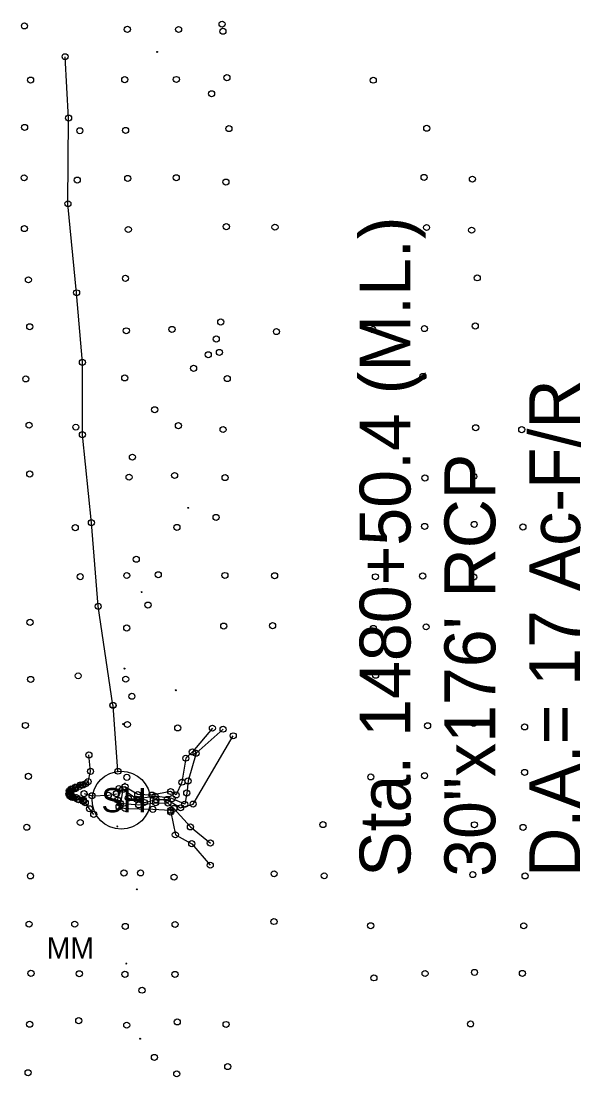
# Model space of a CAD drawing. Extents: x 20503438 to 20508873, y 7964251 to 7984667.
# Drawn here: x 20505530.1 to 20505714.9, y 7980570.4 to 7980918.8 of the extents above; entities that cross this region are included whole.
import ezdxf

# ---------------------------------------------------------------- set-up
doc = ezdxf.new("R2010")
doc.units = 0
for name, color, linetype in [('SurBreakLine', 7, 'Continuous'), ('SurConcreteSlab', 7, 'Continuous'), ('SurControl', 7, 'Continuous'), ('SurDrainageArrowDown', 7, 'Continuous'), ('SurDrainageArrowUp', 7, 'Continuous'), ('SurNaturalCells', 7, 'Continuous'), ('SurPointsNonDTM', 7, 'Continuous'), ('SurRoadPoints', 7, 'Continuous'), ('SurSurveyPoints', 7, 'Continuous'), ('SurTopOfWater', 7, 'Continuous'), ('SurTxtDrainage', 7, 'Continuous')]:
    doc.layers.add(name, color=color, linetype=linetype)

msp = doc.modelspace()

# ---------------------------------------------------------------- linework, layer by layer
at = {"layer": 'SurBreakLine'}
for points in [[(20505593.25, 7980685.48), (20505586.62, 7980677.63), (20505584.46, 7980675.57), (20505583.18, 7980667.65), (20505581.29, 7980663.44), (20505579.46, 7980664.57), (20505573.29, 7980663.41), (20505568.59, 7980663.55), (20505564.39, 7980666.13), (20505562.35, 7980665.55), (20505561.96, 7980661.76), (20505562.45, 7980659.56), (20505564.42, 7980658.97), (20505573.58, 7980658.7), (20505579.42, 7980658.39), (20505579.48, 7980657.79), (20505581.01, 7980650.28), (20505586.41, 7980647.36), (20505592.52, 7980640.26)], [(20505596.76, 7980685.14), (20505587.84, 7980677.2), (20505585.2, 7980668.06), (20505584.76, 7980664.08), (20505584.12, 7980660.36), (20505579.9, 7980662.22), (20505574.32, 7980663.04), (20505568.35, 7980662.01), (20505563.72, 7980665.25), (20505562.88, 7980660.68), (20505568.9, 7980660.15), (20505574.48, 7980660.89), (20505578.57, 7980660.76), (20505580.53, 7980658.99), (20505585.97, 7980652.88), (20505592.56, 7980647.58)], [(20505554.07, 7980657.04), (20505552.67, 7980658.89), (20505551.27, 7980660.88), (20505550.63, 7980661.3), (20505548.79, 7980661.96), (20505546.91, 7980662.62), (20505546.22, 7980663.1), (20505545.88, 7980663.78), (20505546, 7980664.76), (20505546.64, 7980665.44), (20505547.98, 7980665.99), (20505549.76, 7980666.79), (20505551.38, 7980667.16), (20505552.23, 7980667.86), (20505553.01, 7980671.22), (20505552.47, 7980676.64)]]:
    msp.add_lwpolyline(points, dxfattribs=at)
at = {"layer": 'SurConcreteSlab'}
msp.add_lwpolyline([(20505550.65, 7980661.76), (20505548.37, 7980662.59), (20505547.16, 7980662.9), (20505546.57, 7980663.4), (20505546.41, 7980664.4), (20505546.98, 7980665.15), (20505547.96, 7980665.54), (20505549.43, 7980666.23), (20505550.5, 7980666.74), (20505550.38, 7980666.77), (20505548.14, 7980666.04), (20505546.54, 7980665.32), (20505546.22, 7980664.66), (20505546.12, 7980663.72), (20505546.41, 7980663.08), (20505547.24, 7980662.61), (20505549.17, 7980661.88), (20505550.65, 7980661.46)], close=True, dxfattribs=at)
at = {"layer": 'SurControl'}
for centre in [(20505575, 7980908.67), (20505585.26, 7980758.19), (20505569.89, 7980730.41), (20505564.21, 7980705.13), (20505581.15, 7980697.99), (20505563.79, 7980686.85), (20505564.36, 7980667.23), (20505561.86, 7980653.07), (20505568.27, 7980632.29), (20505564.83, 7980607.76), (20505569.39, 7980582.97)]:
    msp.add_circle(centre, 0.15, dxfattribs=at)
at = {"layer": 'SurDrainageArrowDown'}
for points in [[(20505565.47, 7980662.37), (20505570.79, 7980660.96), (20505574.66, 7980661.89), (20505578.32, 7980661.96), (20505582.74, 7980659.2), (20505586.88, 7980660.43), (20505600.12, 7980682.96)], [(20505550.87, 7980663.87), (20505553.51, 7980663.17), (20505558.93, 7980663.32), (20505561.57, 7980663.83)]]:
    msp.add_lwpolyline(points, dxfattribs=at)
at = {"layer": 'SurDrainageArrowUp'}
msp.add_lwpolyline([(20505562.07, 7980671.28), (20505560.47, 7980692.97), (20505560.41, 7980693.07), (20505555.54, 7980725.73), (20505553.29, 7980753.28), (20505550.34, 7980782.34), (20505550.32, 7980806.21), (20505548.41, 7980829.17), (20505545.55, 7980858.54), (20505545.77, 7980886.85), (20505544.63, 7980907.09)], dxfattribs=at)
at = {"layer": 'SurNaturalCells'}
msp.add_circle((20505563.15, 7980661.72), 9.59, dxfattribs=at)
at = {"layer": 'SurPointsNonDTM'}
for centre in [(20505596.44, 7980917.84), (20505596.01, 7980819.54), (20505594.52, 7980813.92), (20505595.57, 7980809.49), (20505587.03, 7980804.24), (20505574.19, 7980790.59), (20505566.85, 7980774.93), (20505594.47, 7980755.03), (20505568.1, 7980741.22), (20505575.38, 7980736.13), (20505571.98, 7980726.12), (20505566.66, 7980696), (20505569.52, 7980637.69), (20505570.01, 7980599), (20505574.09, 7980576.82), (20505598.3, 7980573.8)]:
    msp.add_circle(centre, 1, dxfattribs=at)
at = {"layer": 'SurSurveyPoints'}
for centre in [(20505531.21, 7980917.24), (20505565.17, 7980916.12), (20505582.07, 7980916.08), (20505596.7, 7980915.5), (20505544.63, 7980907.09), (20505533.24, 7980899.38), (20505564.3, 7980899.52), (20505581.34, 7980899.58), (20505598.02, 7980900.17), (20505646.33, 7980899.34), (20505592.97, 7980894.87), (20505545.77, 7980886.85), (20505531.25, 7980883.77), (20505549.48, 7980882.67), (20505564.6, 7980882.76), (20505598.71, 7980883.38), (20505664, 7980883.49), (20505531.1, 7980867.12), (20505581.3, 7980867.15), (20505663.11, 7980867.26), (20505548.63, 7980866.38), (20505565.31, 7980866.93), (20505597.72, 7980865.71), (20505679.08, 7980866.68), (20505545.55, 7980858.54), (20505531.19, 7980850.36), (20505565.49, 7980850.06), (20505597.84, 7980851), (20505613.9, 7980850.83), (20505663.92, 7980850.72), (20505678.82, 7980849.84), (20505532.52, 7980833.45), (20505564.55, 7980833.95), (20505680.68, 7980834.1), (20505548.41, 7980829.17), (20505532.94, 7980817.98), (20505564.83, 7980816.63), (20505579.9, 7980817.09), (20505614.39, 7980816.36), (20505646.2, 7980817.02), (20505663.24, 7980817.37), (20505680.02, 7980818.21), (20505591.87, 7980808.72), (20505550.32, 7980806.21), (20505564.32, 7980801.08), (20505662.72, 7980801.58), (20505531.65, 7980800.74), (20505598.15, 7980800.86), (20505532.72, 7980785.48), (20505548.16, 7980784.83), (20505582.02, 7980785.32), (20505596.76, 7980784.05), (20505680.15, 7980784.63), (20505695.34, 7980784), (20505550.34, 7980782.34), (20505532.95, 7980769.36), (20505565.75, 7980768.32), (20505580.76, 7980768.88), (20505597.44, 7980768.18), (20505663.4, 7980768.04), (20505679.51, 7980768.57), (20505553.29, 7980753.28), (20505679.65, 7980752.73), (20505547.97, 7980751.66), (20505581.52, 7980751.74), (20505663.3, 7980752.08), (20505695.75, 7980751.87), (20505549.6, 7980735.48), (20505564.99, 7980735.86), (20505597.37, 7980735.88), (20505613.77, 7980735.79), (20505647.05, 7980735.44), (20505662.65, 7980735.7), (20505679.49, 7980735.37), (20505555.54, 7980725.73), (20505533.04, 7980720.42), (20505564.96, 7980718.54), (20505597, 7980719.16), (20505613.1, 7980719.31), (20505646.4, 7980718.42), (20505663.79, 7980718.92), (20505533.26, 7980701.56), (20505548.93, 7980702.75), (20505564.64, 7980701.65), (20505647.11, 7980702.95), (20505560.41, 7980693.07), (20505560.47, 7980692.97), (20505531.51, 7980686.37), (20505565.19, 7980686.69), (20505664.28, 7980686.27), (20505679.43, 7980687.11), (20505581.79, 7980685.57), (20505593.25, 7980685.48), (20505596.76, 7980685.14), (20505600.12, 7980682.96), (20505696.3, 7980685.88), (20505552.47, 7980676.64), (20505584.46, 7980675.57), (20505586.62, 7980677.63), (20505587.84, 7980677.2), (20505532.51, 7980669.59), (20505553.01, 7980671.22), (20505562.07, 7980671.28), (20505565, 7980669.26), (20505645.53, 7980669.4), (20505663.26, 7980669.79), (20505696.28, 7980670.87), (20505546.54, 7980665.32), (20505546.64, 7980665.44), (20505546.98, 7980665.15), (20505547.96, 7980665.54), (20505547.98, 7980665.99), (20505548.14, 7980666.04), (20505549.43, 7980666.23), (20505549.76, 7980666.79), (20505550.38, 7980666.77), (20505550.5, 7980666.74), (20505551.38, 7980667.16), (20505552.23, 7980667.86), (20505562.35, 7980665.55), (20505563.72, 7980665.25), (20505564.39, 7980666.13), (20505583.18, 7980667.65), (20505585.2, 7980668.06), (20505545.88, 7980663.78), (20505546, 7980664.76), (20505546.12, 7980663.72), (20505546.22, 7980664.66), (20505546.22, 7980663.1), (20505546.41, 7980664.4), (20505546.41, 7980663.08), (20505546.57, 7980663.4), (20505546.91, 7980662.62), (20505547.16, 7980662.9), (20505547.24, 7980662.61), (20505548.37, 7980662.59), (20505548.79, 7980661.96), (20505549.17, 7980661.88), (20505550.65, 7980661.76), (20505550.87, 7980663.87), (20505553.51, 7980663.17), (20505558.93, 7980663.32), (20505561.57, 7980663.83), (20505561.96, 7980661.76), (20505565.47, 7980662.37), (20505568.35, 7980662.01), (20505568.59, 7980663.55), (20505573.29, 7980663.41), (20505574.32, 7980663.04), (20505574.66, 7980661.89), (20505578.32, 7980661.96), (20505579.46, 7980664.57), (20505579.9, 7980662.22), (20505581.29, 7980663.44), (20505584.76, 7980664.08), (20505550.63, 7980661.3), (20505550.65, 7980661.46), (20505551.27, 7980660.88), (20505552.67, 7980658.89), (20505562.45, 7980659.56), (20505562.88, 7980660.68), (20505564.42, 7980658.97), (20505568.9, 7980660.15), (20505570.79, 7980660.96), (20505573.58, 7980658.7), (20505574.48, 7980660.89), (20505578.57, 7980660.76), (20505579.42, 7980658.39), (20505580.53, 7980658.99), (20505582.74, 7980659.2), (20505584.12, 7980660.36), (20505586.88, 7980660.43), (20505554.07, 7980657.04), (20505579.48, 7980657.79), (20505531.98, 7980652.77), (20505549.61, 7980654.35), (20505585.97, 7980652.88), (20505629.72, 7980653.65), (20505679.73, 7980653.59), (20505695.79, 7980652.74), (20505581.01, 7980650.28), (20505592.56, 7980647.58), (20505586.41, 7980647.36), (20505564.06, 7980637.67), (20505592.52, 7980640.26), (20505613.62, 7980637.41), (20505679.2, 7980637.16), (20505533.19, 7980636.71), (20505580.59, 7980636.31), (20505630.14, 7980636.75), (20505696.45, 7980636.7), (20505532.74, 7980620.8), (20505547.81, 7980620.79), (20505564.47, 7980620.06), (20505580.92, 7980620.69), (20505613.57, 7980621.66), (20505645.49, 7980620.26), (20505696.02, 7980620.25), (20505533.36, 7980604.56), (20505549.31, 7980604.42), (20505564.38, 7980604.23), (20505580.89, 7980604.22), (20505646.55, 7980603.07), (20505663.43, 7980604.51), (20505679.76, 7980604.87), (20505695.57, 7980604.53), (20505549.13, 7980588.94), (20505581.64, 7980588.54), (20505532.93, 7980587.75), (20505564.97, 7980587.46), (20505597.75, 7980587.69), (20505678.44, 7980587.87), (20505532.4, 7980571.76), (20505581.46, 7980571.39)]:
    msp.add_circle(centre, 1, dxfattribs=at)
at = {"layer": 'SurTopOfWater'}
for points in [[(20505566.69, 7980661.69), (20505566.73, 7980661.69), (20505566.73, 7980661.73), (20505566.69, 7980661.73)], [(20505566.71, 7980661.74), (20505566.71, 7980661.74), (20505566.71, 7980661.7), (20505566.71, 7980661.7)], [(20505566.71, 7980661.74), (20505566.71, 7980661.74), (20505566.71, 7980661.72), (20505566.71, 7980661.72)], [(20505566.71, 7980661.72), (20505566.71, 7980661.72), (20505566.71, 7980661.71), (20505566.71, 7980661.71)], [(20505566.71, 7980661.71), (20505566.71, 7980661.71), (20505566.71, 7980661.7), (20505566.71, 7980661.7)]]:
    msp.add_lwpolyline(points, close=True, dxfattribs=at)
for centre in [(20505566.7, 7980661.71), (20505566.71, 7980661.71), (20505566.72, 7980661.71)]:
    msp.add_arc(centre, 0.00586, 186.3566, 5.6839, dxfattribs=at)

# ---------------------------------------------------------------- texts
at = {"layer": 'SurNaturalCells'}
msp.add_text('SH', height=7.995, rotation=360, dxfattribs=at).set_placement((20505556.63, 7980657.72))
at = {"layer": 'SurRoadPoints'}
msp.add_text('MM', height=6.995, rotation=360, dxfattribs=at).set_placement((20505538.58, 7980609.44))
at = {"layer": 'SurTxtDrainage'}
for s, p in [('Sta. 1480+50.4 (M.L.)', (20505658.63, 7980636.41)), ('D.A.= 17 Ac-F/R', (20505714.63, 7980636.41)), ('30"x176\' RCP', (20505686.63, 7980636.41))]:
    msp.add_text(s, height=16.8, rotation=90, dxfattribs=at).set_placement(p)

doc.saveas('drawing.dxf')
